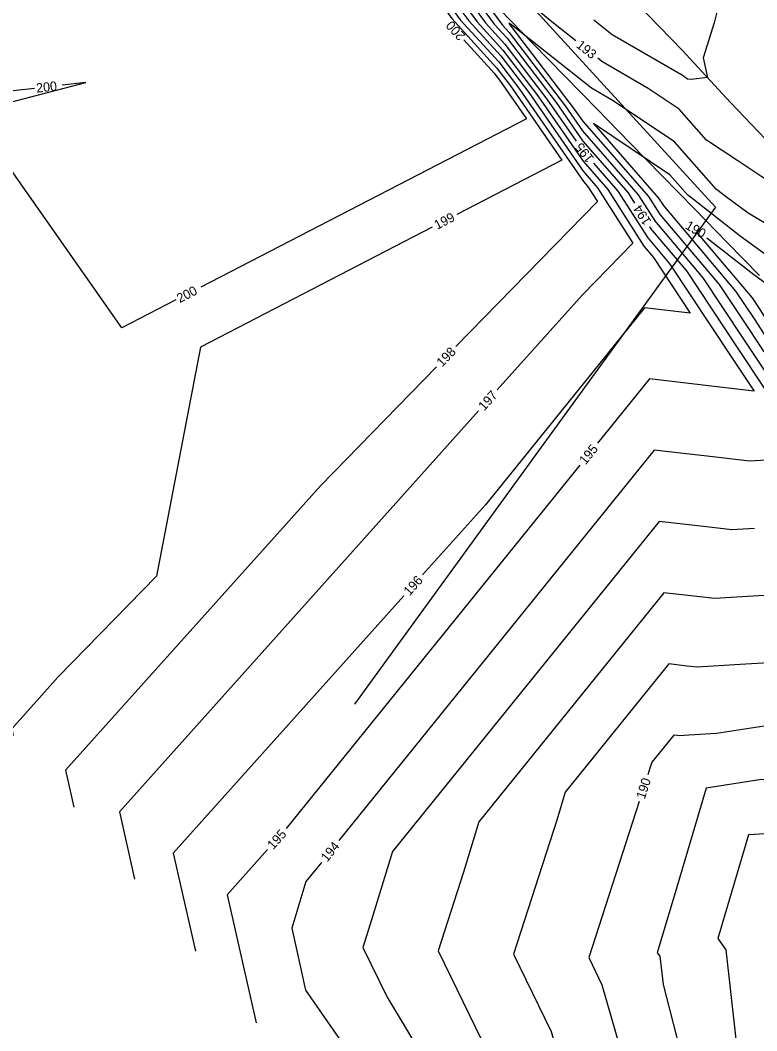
# Model space of a CAD drawing. Extents: x 2086416 to 2115205, y 575507 to 632762.
# Drawn here: x 2110120.8 to 2110278.4, y 581864.8 to 582081.1 of the extents above; entities that cross this region are included whole.
import ezdxf

# ---------------------------------------------------------------- set-up
doc = ezdxf.new("R2010")
doc.units = 0
for name, color, linetype in [('DTM Contours Major', 7, 'Continuous'), ('DTM Contours Major Text', 7, 'Continuous'), ('DTM Contours Minor', 7, 'Continuous'), ('DTM Contours Minor Text', 7, 'Continuous'), ('Exist Hydrographic FEMA Cross Section', 7, 'Continuous'), ('Exist Roads EOP', 7, 'Continuous'), ('Exist Vegetation Woods Line', 7, 'Continuous')]:
    doc.layers.add(name, color=color, linetype=linetype)

msp = doc.modelspace()

# ---------------------------------------------------------------- linework, layer by layer
at = {"layer": 'DTM Contours Major'}
for points in [[(2110178.7, 582134.27), (2110181.09, 582131.08), (2110193.25, 582116.59), (2110196.34, 582111.83), (2110207.38, 582098.6), (2110208.2, 582097.27), (2110210.42, 582094.03), (2110220.36, 582080.52), (2110224.5, 582075.98), (2110233.47, 582064.23), (2110239.72, 582055.18)], [(2110123.82, 582066.52), (2110108.81, 582064.84), (2110104.3, 582064.09), (2110105.52, 582086.17), (2110100.43, 582086.39), (2110097.21, 582099.07), (2110089.24, 582085.01), (2110086.09, 582069.62), (2110086.03, 582061.46)], [(2110215.68, 582076.9), (2110222.27, 582069.67), (2110223.71, 582067.79), (2110229.08, 582060.02), (2110159.44, 582023.99)], [(2110154.11, 582021.23), (2110142.55, 582015.25), (2110110.16, 582061.32), (2110134.87, 582067.76), (2110129.78, 582067.19)], [(2110243.44, 582050.48), (2110248.66, 582044.49), (2110255.03, 582034.5), (2110255.1, 582034.42), (2110259.79, 582028.87), (2110272.96, 582009), (2110277.79, 582001.71), (2110271.7, 582002.43), (2110255.39, 582004.31), (2110244.28, 581990.54)], [(2110265.4, 582035.83), (2110277.36, 582021.68), (2110279.01, 582019.19), (2110279.89, 582017.86), (2110293.32, 581998.29), (2110298.98, 581988.65), (2110301.29, 581985.18), (2110308.53, 581973.54), (2110318.39, 581956.29), (2110318.49, 581956.12), (2110321.45, 581953.37)], [(2110346.2, 581972.79), (2110341.33, 581976.42), (2110337.08, 581979.04), (2110330.74, 581983.65), (2110321.37, 581992.65), (2110319.17, 581994.09), (2110305.61, 582003.68), (2110304.12, 582004.86), (2110297.71, 582010.63), (2110285.4, 582020.11), (2110281.57, 582023.82), (2110277.77, 582026.61), (2110267.71, 582034.46)], [(2110240.51, 581985.87), (2110177.7, 581908.06)], [(2110324.46, 581948.27), (2110332.16, 581932.18), (2110294.81, 581932.29), (2110269.72, 581928.4), (2110263.82, 581928.04), (2110261.87, 581927.92), (2110261.42, 581927.97), (2110260.59, 581928.07), (2110255.91, 581922.27), (2110255.52, 581921), (2110255.06, 581919.59)], [(2110253.22, 581913.88), (2110242.42, 581880.48), (2110245.25, 581874.66), (2110250.14, 581857.58), (2110257.38, 581829.58), (2110260.82, 581819.81), (2110261.06, 581819.65), (2110261.31, 581818.59)], [(2110173.71, 581903.58), (2110165.05, 581893.91), (2110171.25, 581866.48)]]:
    msp.add_lwpolyline(points, dxfattribs=at)
at = {"layer": 'DTM Contours Minor'}
for points in [[(2110129.99, 582188.77), (2110137.86, 582180.13), (2110142.58, 582173.94), (2110152.95, 582165.38), (2110159.37, 582156.53), (2110166.99, 582145.24), (2110171.43, 582139.52), (2110180.53, 582127.38), (2110186.6, 582120.16), (2110197.14, 582103.95), (2110201.12, 582099.16), (2110203.74, 582094.97), (2110210.77, 582084.66), (2110213.14, 582081.44), (2110222.72, 582070.93), (2110225.66, 582067.07), (2110236.67, 582051.15), (2110214.22, 582039.54)], [(2110150.93, 582167.76), (2110153.27, 582165.82), (2110161.17, 582154.95), (2110167.28, 582145.9), (2110173.19, 582138.29), (2110180.67, 582128.31), (2110188.26, 582119.27), (2110196.94, 582105.92), (2110202.69, 582099.02), (2110204.85, 582095.54), (2110210.68, 582087), (2110214.95, 582081.21), (2110223.16, 582072.19), (2110227.61, 582066.36), (2110241.27, 582046.6), (2110242.14, 582045.61), (2110244.26, 582042.28), (2110214.02, 582011.24)], [(2110158.44, 582159.61), (2110162.98, 582153.37), (2110167.58, 582146.55), (2110174.95, 582137.05), (2110180.81, 582129.23), (2110189.92, 582118.37), (2110196.74, 582107.89), (2110204.25, 582098.88), (2110205.97, 582096.12), (2110210.59, 582089.35), (2110216.75, 582080.98), (2110223.61, 582073.45), (2110229.57, 582065.65), (2110241.24, 582048.76), (2110244.31, 582045.24), (2110251.86, 582033.4), (2110241.09, 582022.35), (2110222.86, 582001.98)], [(2110195.51, 582111.45), (2110196.54, 582109.86), (2110205.81, 582098.74), (2110207.08, 582096.7), (2110210.51, 582091.69), (2110218.55, 582080.75), (2110224.05, 582074.71), (2110231.52, 582064.94), (2110241.21, 582050.92), (2110246.49, 582044.86), (2110254.2, 582032.77), (2110254.23, 582032.74), (2110256.28, 582030.31), (2110264.15, 582018.43), (2110254.35, 582019.56), (2110220.3, 581977.38), (2110206.86, 581962.37)], [(2110210.33, 582096.37), (2110222.16, 582080.29), (2110224.94, 582077.24), (2110235.42, 582063.52), (2110241.15, 582055.24), (2110250.84, 582044.12), (2110252.22, 582041.95)], [(2110239.63, 582076.69), (2110234.85, 582080.48), (2110227.63, 582086.48), (2110212.34, 582095.86), (2110223.97, 582080.06), (2110225.38, 582078.5), (2110237.38, 582062.8), (2110241.12, 582057.39), (2110253.02, 582043.75), (2110256.71, 582037.96), (2110256.86, 582037.78), (2110266.82, 582025.99), (2110275.38, 582013.07), (2110279.92, 582006.23), (2110285.03, 581998.78), (2110298.39, 581976.04), (2110298.49, 581975.89), (2110298.8, 581975.39), (2110299.81, 581973.62), (2110296.89, 581973.45), (2110283.89, 581972.66)], [(2110270.15, 582084.25), (2110269.26, 582080.53), (2110266.92, 582073.07), (2110267.79, 582068.83), (2110264.3, 582068.4), (2110263.54, 582068.5), (2110262.95, 582068.88), (2110262.79, 582069.07), (2110262.6, 582069.2), (2110247.4, 582078), (2110243.48, 582081.11)], [(2110283.74, 582035.52), (2110276.51, 582039.81), (2110271.87, 582043.2), (2110269.72, 582044.88), (2110269.68, 582044.91), (2110260.78, 582055.04), (2110247.67, 582063.83), (2110243, 582066.54), (2110226.22, 582079.84), (2110225.92, 582080.09), (2110225.29, 582080.48), (2110225.77, 582079.83), (2110225.83, 582079.76), (2110239.33, 582062.09), (2110241.09, 582059.55), (2110255.19, 582043.38), (2110257.54, 582039.69), (2110257.73, 582039.46), (2110270.33, 582024.56), (2110276.59, 582015.11), (2110279.91, 582010.11)], [(2110286.44, 582081.48), (2110287.22, 582079.93), (2110289.28, 582077.11), (2110289.71, 582074.07), (2110290.54, 582072.75), (2110291.77, 582065.16), (2110289.82, 582058.59), (2110291.13, 582049.84), (2110291.2, 582043.81), (2110290.42, 582042.42), (2110287.21, 582043.02), (2110284.81, 582044.52), (2110282.98, 582045.45), (2110279.43, 582047.55), (2110274.33, 582051.01), (2110267.62, 582055.41), (2110261.78, 582062.06), (2110255.13, 582066.52), (2110245.2, 582072.27), (2110244.33, 582072.96)], [(2110323.07, 582000.02), (2110308.3, 582006.54), (2110306.38, 582007.9), (2110306.25, 582008), (2110296.94, 582016.39), (2110293.07, 582019.36), (2110283.91, 582028.25), (2110274.82, 582034.9), (2110263.82, 582043.5), (2110263.61, 582043.67), (2110259.77, 582048.03), (2110243.43, 582058.99), (2110257.37, 582043), (2110258.38, 582041.42), (2110258.61, 582041.15), (2110273.85, 582023.12), (2110277.8, 582017.15), (2110279.9, 582013.99), (2110290.56, 581998.46), (2110298.79, 581984.45), (2110300.36, 581982.08), (2110302.61, 581978.47)], [(2110208.9, 582036.78), (2110159.35, 582011.14), (2110149.92, 581962.12), (2110128.92, 581940.56), (2110118.98, 581929.46), (2110119.3, 581928.01)], [(2110255.45, 582036.89), (2110255.87, 582036.23), (2110255.98, 582036.1), (2110263.31, 582027.43), (2110274.17, 582011.04), (2110279.93, 582002.35), (2110282.27, 581998.95), (2110289.03, 581987.44), (2110276.79, 581986.7), (2110269.64, 581987.54), (2110256.43, 581989.07), (2110188.99, 581905.51)], [(2110209.84, 582006.94), (2110185.01, 581981.45), (2110130.49, 581920.57), (2110132.29, 581912.63)], [(2110218.86, 581997.51), (2110142.01, 581911.68), (2110145.28, 581897.25)], [(2110301.63, 581975.45), (2110302.04, 581974.77), (2110310.59, 581959.81), (2110285.87, 581958.31), (2110269.33, 581957.31), (2110265.53, 581957.76), (2110258.51, 581958.57), (2110218.92, 581909.52), (2110215.63, 581898.75), (2110210.19, 581881.92), (2110223.48, 581854.62), (2110225.48, 581847.63), (2110225.52, 581847.51)], [(2110310.4, 581975.13), (2110311.78, 581972.92), (2110319.5, 581959.4), (2110319.67, 581959.11), (2110326.46, 581952.81), (2110336.26, 581932.33), (2110337.91, 581930.13), (2110342.94, 581918.36), (2110327.45, 581919.35), (2110326.2, 581920.21), (2110297.45, 581918.49), (2110279.39, 581918.55), (2110267.52, 581916.71), (2110261.26, 581895.57), (2110257.09, 581881.5), (2110257.62, 581880.73), (2110258.31, 581874.72), (2110261.9, 581860.82)], [(2110277.9, 581972.3), (2110273.06, 581972), (2110267.58, 581972.65), (2110257.47, 581973.82), (2110200.42, 581903.14), (2110195.69, 581887.62), (2110194.08, 581882.65), (2110199.28, 581871.96), (2110208.59, 581856.5), (2110209.7, 581844.49), (2110213.48, 581835.41), (2110219.86, 581821.45)], [(2110305.75, 581973.35), (2110317.27, 581953.18), (2110317.3, 581953.14), (2110318.49, 581952.03), (2110321.38, 581945.99), (2110310.24, 581946.03), (2110302.75, 581944.87), (2110274.84, 581943.18), (2110265.6, 581942.62), (2110263.47, 581942.87), (2110259.55, 581943.32), (2110237.41, 581915.9), (2110235.58, 581909.87), (2110226.31, 581881.2), (2110234.36, 581864.64), (2110238.85, 581848.99)], [(2110202.86, 581957.9), (2110153.53, 581902.8), (2110158.27, 581881.87)], [(2110347.71, 581918.62), (2110353.65, 581904.72), (2110353.7, 581904.68), (2110353.7, 581904.67), (2110353.73, 581904.55), (2110353.54, 581904.51), (2110353.43, 581904.57), (2110316.59, 581906.92), (2110313.59, 581908.97), (2110276.62, 581906.77), (2110270.04, 581884.58), (2110271.75, 581882.11), (2110273.92, 581863.02), (2110279.51, 581841.39), (2110280.82, 581837.67), (2110289.39, 581831.97), (2110290.63, 581826.76), (2110299.16, 581809.22)], [(2110185.22, 581900.84), (2110181.93, 581896.76), (2110178.88, 581886.78), (2110181.8, 581873.46), (2110190.57, 581860.89), (2110193.02, 581841.51)]]:
    msp.add_lwpolyline(points, dxfattribs=at)
at = {"layer": 'Exist Hydrographic FEMA Cross Section'}
msp.add_lwpolyline([(2110278.97, 582026.43), (2110272.04, 582033.54), (2110265.1, 582040.65), (2110258.16, 582047.77), (2110251.22, 582054.88), (2110244.28, 582061.99), (2110237.34, 582069.1), (2110230.4, 582076.22), (2110223.46, 582083.33)], dxfattribs=at)
at = {"layer": 'Exist Roads EOP'}
msp.add_lwpolyline([(2110044.03, 582306.54), (2110057.72, 582292.25), (2110067.42, 582282.08), (2110077.05, 582271.73), (2110082.67, 582265.54), (2110091.18, 582256.81), (2110101.9, 582244.92), (2110112.61, 582233.51), (2110124.83, 582220.15), (2110138.66, 582205.71), (2110150.44, 582192.87), (2110163.31, 582179.2), (2110176.51, 582165.18), (2110187.09, 582154.1), (2110200.16, 582140.29), (2110212.15, 582128.06), (2110221.2, 582117.92), (2110235.62, 582102.6), (2110247.94, 582089.65), (2110262.41, 582074.68), (2110272.71, 582063.48), (2110283.25, 582052.48)], dxfattribs=at)
at = {"layer": 'Exist Vegetation Woods Line'}
for points in [[(2110068.55, 582251.65), (2110094.73, 582231.68), (2110124.29, 582202.28), (2110166.88, 582155.97), (2110198.23, 582122.47), (2110225.6, 582089.15), (2110269.57, 582041.09)], [(2110269.57, 582041.09), (2110192.31, 581934.72)]]:
    msp.add_lwpolyline(points, dxfattribs=at)

# ---------------------------------------------------------------- texts
at = {"layer": 'DTM Contours Major Text'}
for s, rotation, p in [('200', 132.3236, (2110216.16, 582077.87)), ('200', 6.3934, (2110124.32, 582065.57)), ('195', 128.3436, (2110243.66, 582051.58)), ('190', 329.3568, (2110262.88, 582036.61)), ('200', 27.3573, (2110154.92, 582020.52)), ('195', 51.0913, (2110241.74, 581985.81)), ('190', 72.0874, (2110254.39, 581914.26)), ('195', 48.2566, (2110174.94, 581903.45))]:
    msp.add_text(s, height=2, rotation=rotation, dxfattribs=at).set_placement(p)
at = {"layer": 'DTM Contours Minor Text'}
for s, rotation, p in [('193', 321.5901, (2110239.58, 582075.45)), ('194', 122.5143, (2110255.9, 582038.04)), ('199', 27.3573, (2110210, 582036.22)), ('198', 45.7465, (2110211.06, 582006.76)), ('197', 48.1605, (2110220.08, 581997.38)), ('196', 48.1605, (2110204.09, 581957.77)), ('194', 51.0913, (2110186.46, 581900.78))]:
    msp.add_text(s, height=2, rotation=rotation, dxfattribs=at).set_placement(p)

doc.saveas('drawing.dxf')
